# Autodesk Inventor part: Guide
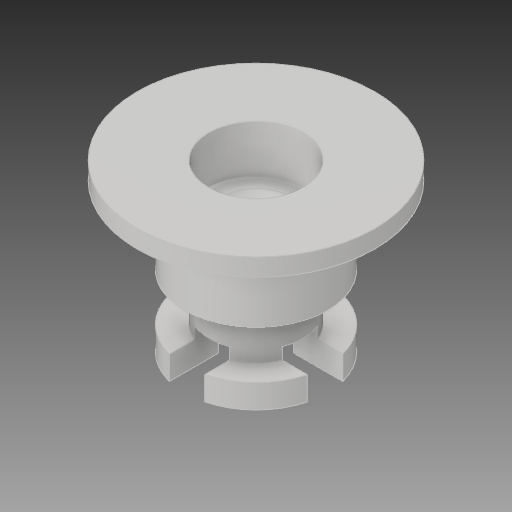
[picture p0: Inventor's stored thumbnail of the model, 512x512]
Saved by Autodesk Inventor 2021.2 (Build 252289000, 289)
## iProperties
Created: 2018-06
Part Number: Guide
Material: Plastique ABS
Document SubType Name: Modeling
Designer: Fabian Perrée
Density: 1.06 g/cm^3
Appearance: Lisse - Blanc
Author: Fabian Perrée
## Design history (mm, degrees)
sketch "Esquisse1"
  geometry: L1 (0, 0)-(0, 14); L2 (0, 14)-(10, 14); L3 (10, 14)-(10, 12.5); L4 (10, 12.5)-(6, 12.5); L5 (6, 12.5)-(6, 6); L6 (6, 6)-(4, 6); L7 (4, 6)-(4, 2); L8 (4, 2)-(6, 2); L9 (6, 2)-(6, 0); L10 (6, 0)-(0, 0); L11 (4, 14)-(4, 10); L12 (4, 10)-(2.25, 10); L13 (2.25, 10)-(2.25, 3); L14 (2.25, 3)-(0, 3)
  constraints: 28 end point, 12 perpendicular, 2 point on line, 2 vertical, 1 collinear
  dimensions: "d0" = 14 distance of L1.start L1.end; "d2" = 1.5 distance of L2.end L3.end; "d3" = 20 diameter of L3 L1; "d5" = 12 diameter of L5 L1; "d6" = 8 diameter of L7 L1; "d7" = 6.5 distance of L4.end L5.end; "d8" = 4 distance of L6.end L7.end; "d9" = 2 distance of L8.end L9.end (derived); "d10" = 8 diameter of L11 L1; "d11" = 4.5 diameter of L13 L1; "d12" = 4 distance of L11.start L11.end; "d13" = 3 distance between parallel lines of L10 L14
revolve "Révolution1" sketch "Esquisse1" stored, may be unused: angle "d14" = 90 deg
sketch "Esquisse2"
  geometry: L1 (6, 1.5)-(0, 1.5); L2 (0, 1.5)-(0, -1.5); L3 (0, -1.5)-(6, -1.5); L4 (6, -1.5)-(6, 1.5); L5 (0, 0)-(10, 0); C1 r 6 at (0, 0) reference; 1 further point
  constraints: 10 end point, 2 parallel, 1 horizontal, 1 horizontal alignment, 1 midpoint, 1 perpendicular, 1 tangent, 2 other
  dimensions: "d15" = 3 distance of L3.end L1.start
extrude "Extrusion1" cut sketch "Esquisse2" distance "d16" = 3; taper "d17" = 0 deg
pattern_circular "Réseau circulaire1" dims angle "d19" = 360 deg
chamfer "Chanfrein1" distance "d21" = 0.5; stored, may be unused: second distance "d22" = 2, angle "d23" = 45 deg
sketch "Esquisse3"
  geometry: C1 r 2.25 at (0, 0); A1 r 2.25 centre (0, 0) between (-1.5, -1.677) and (1.5, -1.677) reference
  constraints: 1 centre point, 1 coincident, 1 concentric
extrude "Extrusion2" cut sketch "Esquisse3" extent not by distance; stored distance "d24" = 10; taper "d25" = 0 deg
node "Solide1"
